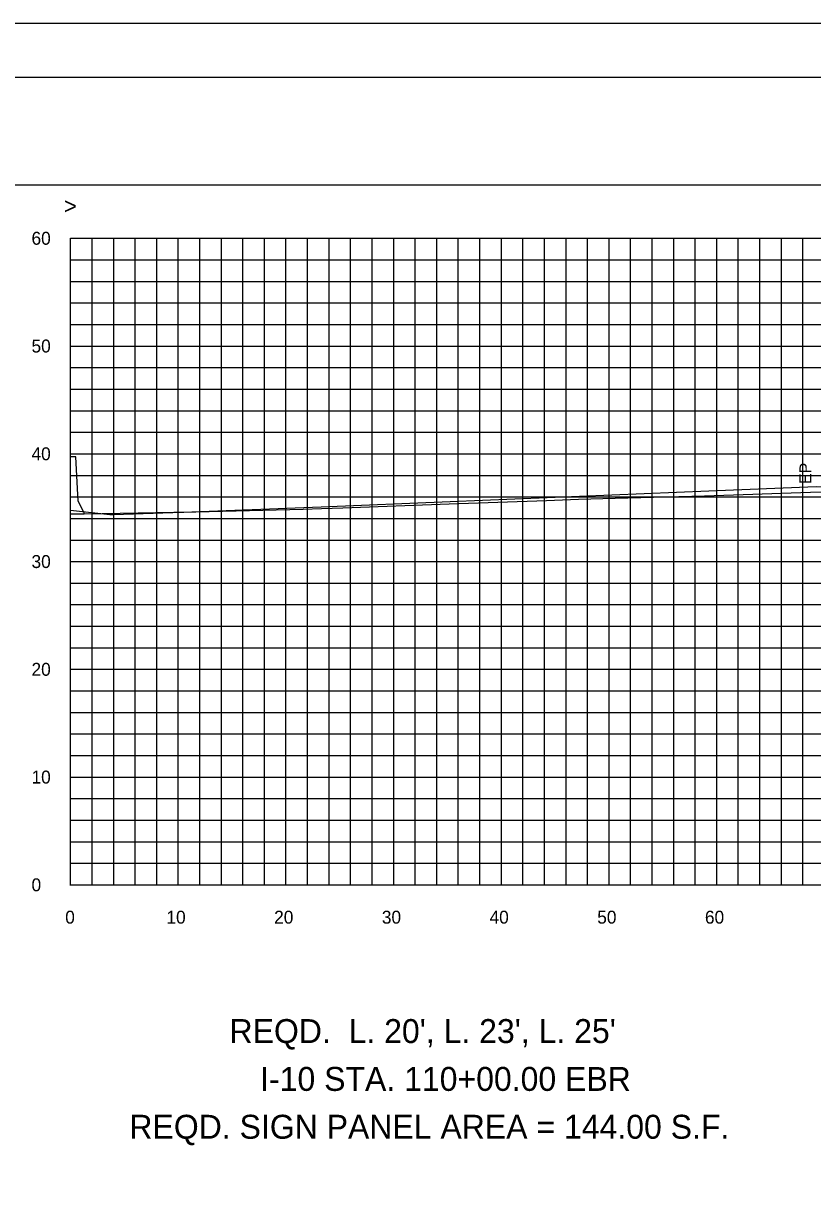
# Model space of a CAD drawing. Extents: x 2193008 to 2198143, y 1236112 to 1237864.
# Drawn here: x 2195038.5 to 2195111.7, y 1237228.8 to 1237338 of the extents above; entities that cross this region are included whole.
import ezdxf

# ---------------------------------------------------------------- set-up
doc = ezdxf.new("R2010")
doc.units = 0
for name, color, linetype in [('31', 7, 'Continuous'), ('60', 7, 'Continuous'), ('Default', 7, 'Continuous'), ('Level 55', 7, 'Continuous'), ('LIMT-CSLINE', 7, 'Continuous'), ('M-ROADS', 7, 'Continuous'), ('SHT-BNDRY', 7, 'Continuous')]:
    doc.layers.add(name, color=color, linetype=linetype)

msp = doc.modelspace()

# ---------------------------------------------------------------- linework, layer by layer
msp.add_lwpolyline([(2194882.86, 1237133.05), (2195182.86, 1237133.05), (2195182.86, 1237323.05), (2194882.86, 1237323.05)], close=True)
at = {"layer": '60'}
for p, q in [((2195042.86, 1237258.11), (2195042.86, 1237318.11)), ((2195042.86, 1237258.05), (2195042.86, 1237258.11)), ((2195042.86, 1237258.11), (2195172.86, 1237258.11)), ((2195052.86, 1237258.05), (2195052.86, 1237258.11)), ((2195062.86, 1237258.05), (2195062.86, 1237258.11)), ((2195072.86, 1237258.05), (2195072.86, 1237258.11)), ((2195082.86, 1237258.05), (2195082.86, 1237258.11)), ((2195092.86, 1237258.05), (2195092.86, 1237258.11)), ((2195102.86, 1237258.05), (2195102.86, 1237258.11))]:
    msp.add_line(p, q, dxfattribs=at)
msp.add_lwpolyline([(2195042.86, 1237292.53), (2195043.92, 1237292.53), (2195044.11, 1237292.53), (2195054.11, 1237292.71), (2195066.11, 1237293.19), (2195078.11, 1237293.68), (2195090.11, 1237294.17), (2195102.11, 1237294.66), (2195112.1, 1237295.07), (2195124.1, 1237294.72), (2195126.1, 1237294.66), (2195127.61, 1237294.6)], dxfattribs=at)
at = {"layer": 'Default'}
msp.add_lwpolyline([(2195042.86, 1237292.53), (2195044.11, 1237292.53), (2195044.11, 1237292.62), (2195044.1, 1237292.7), (2195043.55, 1237293.7), (2195043.36, 1237297.84), (2195042.86, 1237297.84)], dxfattribs=at)
at = {"layer": 'M-ROADS'}
for p, q in [((2195042.86, 1237318.11), (2195172.86, 1237318.11)), ((2195044.86, 1237258.11), (2195044.86, 1237318.11)), ((2195046.86, 1237258.11), (2195046.86, 1237318.11)), ((2195048.86, 1237258.11), (2195048.86, 1237318.11)), ((2195050.86, 1237258.11), (2195050.86, 1237318.11)), ((2195052.86, 1237258.11), (2195052.86, 1237318.11)), ((2195054.86, 1237258.11), (2195054.86, 1237318.11)), ((2195056.86, 1237258.11), (2195056.86, 1237318.11)), ((2195058.86, 1237258.11), (2195058.86, 1237318.11)), ((2195060.86, 1237258.11), (2195060.86, 1237318.11)), ((2195062.86, 1237258.11), (2195062.86, 1237318.11)), ((2195064.86, 1237258.11), (2195064.86, 1237318.11)), ((2195066.86, 1237258.11), (2195066.86, 1237318.11)), ((2195068.86, 1237258.11), (2195068.86, 1237318.11)), ((2195070.86, 1237258.11), (2195070.86, 1237318.11)), ((2195072.86, 1237258.11), (2195072.86, 1237318.11)), ((2195074.86, 1237258.11), (2195074.86, 1237318.11)), ((2195076.86, 1237258.11), (2195076.86, 1237318.11)), ((2195078.86, 1237258.11), (2195078.86, 1237318.11)), ((2195080.86, 1237258.11), (2195080.86, 1237318.11)), ((2195082.86, 1237258.11), (2195082.86, 1237318.11)), ((2195084.86, 1237258.11), (2195084.86, 1237318.11)), ((2195086.86, 1237258.11), (2195086.86, 1237318.11)), ((2195088.86, 1237258.11), (2195088.86, 1237318.11)), ((2195090.86, 1237258.11), (2195090.86, 1237318.11)), ((2195092.86, 1237258.11), (2195092.86, 1237318.11)), ((2195094.86, 1237258.11), (2195094.86, 1237318.11)), ((2195096.86, 1237258.11), (2195096.86, 1237318.11)), ((2195098.86, 1237258.11), (2195098.86, 1237318.11)), ((2195100.86, 1237258.11), (2195100.86, 1237318.11)), ((2195102.86, 1237258.11), (2195102.86, 1237318.11)), ((2195104.86, 1237258.11), (2195104.86, 1237318.11)), ((2195106.86, 1237258.11), (2195106.86, 1237318.11)), ((2195108.86, 1237258.11), (2195108.86, 1237318.11)), ((2195110.86, 1237258.11), (2195110.86, 1237318.11)), ((2195042.86, 1237316.11), (2195172.86, 1237316.11)), ((2195042.86, 1237314.11), (2195172.86, 1237314.11)), ((2195042.86, 1237312.11), (2195172.86, 1237312.11)), ((2195042.86, 1237310.11), (2195172.86, 1237310.11)), ((2195042.86, 1237308.11), (2195172.86, 1237308.11)), ((2195042.86, 1237306.11), (2195172.86, 1237306.11)), ((2195042.86, 1237304.11), (2195172.86, 1237304.11)), ((2195042.86, 1237302.11), (2195172.86, 1237302.11)), ((2195042.86, 1237300.11), (2195172.86, 1237300.11)), ((2195042.86, 1237298.11), (2195172.86, 1237298.11)), ((2195042.86, 1237296.11), (2195172.86, 1237296.11)), ((2195042.86, 1237294.11), (2195172.86, 1237294.11)), ((2195042.86, 1237292.11), (2195172.86, 1237292.11)), ((2195042.86, 1237290.11), (2195172.86, 1237290.11)), ((2195042.86, 1237288.11), (2195172.86, 1237288.11)), ((2195042.86, 1237286.11), (2195172.86, 1237286.11)), ((2195042.86, 1237284.11), (2195172.86, 1237284.11)), ((2195042.86, 1237282.11), (2195172.86, 1237282.11)), ((2195042.86, 1237280.11), (2195172.86, 1237280.11)), ((2195042.86, 1237278.11), (2195172.86, 1237278.11)), ((2195042.86, 1237276.11), (2195172.86, 1237276.11)), ((2195042.86, 1237274.11), (2195172.86, 1237274.11)), ((2195042.86, 1237272.11), (2195172.86, 1237272.11)), ((2195042.86, 1237270.11), (2195172.86, 1237270.11)), ((2195042.86, 1237268.11), (2195172.86, 1237268.11)), ((2195042.86, 1237266.11), (2195172.86, 1237266.11)), ((2195042.86, 1237264.11), (2195172.86, 1237264.11)), ((2195042.86, 1237262.11), (2195172.86, 1237262.11)), ((2195042.86, 1237260.11), (2195172.86, 1237260.11)), ((2195042.86, 1237258.11), (2195172.86, 1237258.11))]:
    msp.add_line(p, q, dxfattribs=at)
msp.add_lwpolyline([(2194857.86, 1237118.04), (2195197.86, 1237118.04), (2195197.86, 1237338.04), (2194857.86, 1237338.04)], close=True, dxfattribs=at)
msp.add_lwpolyline([(2195042.86, 1237292.87), (2195046.5, 1237292.47), (2195046.86, 1237292.48), (2195053.25, 1237292.68), (2195053.36, 1237292.68), (2195054.5, 1237292.73), (2195064.44, 1237292.98), (2195066.15, 1237293.03), (2195068.13, 1237293.1), (2195078.02, 1237293.48), (2195087.04, 1237293.79), (2195090.02, 1237293.89), (2195093.43, 1237293.98), (2195101.72, 1237294.21), (2195111.57, 1237294.54), (2195113.5, 1237294.6)], dxfattribs=at)
at = {"layer": 'SHT-BNDRY'}
msp.add_lwpolyline([(2194870.36, 1237123.04), (2195192.86, 1237123.04), (2195192.86, 1237333.04), (2194870.36, 1237333.04)], close=True, dxfattribs=at)

# ---------------------------------------------------------------- texts
at = {"layer": '31'}
for s, p in [('60', (2195039.23, 1237317.51)), ('50', (2195039.23, 1237307.51)), ('40', (2195039.23, 1237297.51)), ('30', (2195039.23, 1237287.51)), ('20', (2195039.23, 1237277.51)), ('10', (2195039.23, 1237267.51)), ('0', (2195039.23, 1237257.51))]:
    msp.add_text(s, height=1.2, dxfattribs=at).set_placement(p)
at = {"layer": '60'}
msp.add_text('>', height=1.5, dxfattribs=at).set_placement((2195042.25, 1237320.36))
at = {"layer": 'Level 55'}
msp.add_text('EP', height=1.11, rotation=90, dxfattribs=at).set_placement((2195111.65, 1237295.3))
for s, p in [(" REQD.  L. 20', L. 23', L. 25'", (2195056.79, 1237243.43)), ('I-10 STA. 110+00.00 EBR', (2195060.46, 1237238.99)), ('REQD. SIGN PANEL AREA = 144.00 S.F.', (2195048.32, 1237234.55))]:
    msp.add_text(s, height=2.2209, dxfattribs=at).set_placement(p)
at = {"layer": 'LIMT-CSLINE'}
for s, p in [('0', (2195042.36, 1237254.51)), ('10', (2195051.76, 1237254.51)), ('20', (2195061.76, 1237254.51)), ('30', (2195071.76, 1237254.51)), ('40', (2195081.76, 1237254.51)), ('50', (2195091.76, 1237254.51)), ('60', (2195101.76, 1237254.51))]:
    msp.add_text(s, height=1.2, dxfattribs=at).set_placement(p)

doc.saveas('drawing.dxf')
